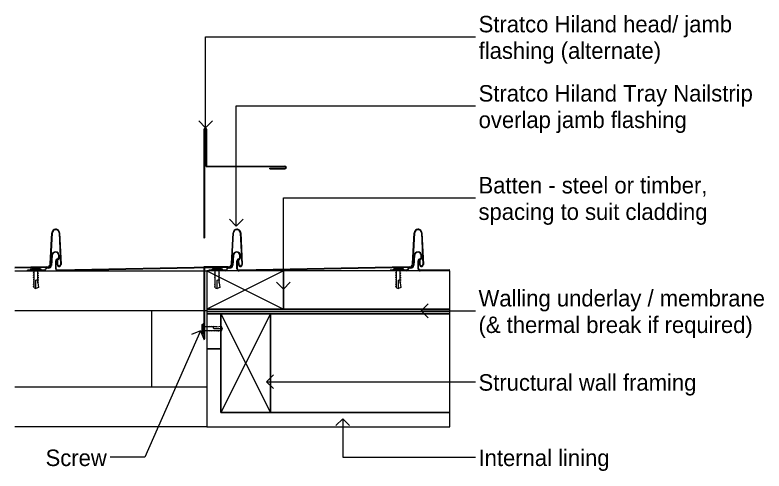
# Model space of a CAD drawing. Extents: x -2.36 to 6.66, y -3.72 to 4.13.
# Drawn here: x 5.981 to 6.663, y -2.182 to -1.767 of the extents above; entities that cross this region are included whole.
import ezdxf

# ---------------------------------------------------------------- set-up
doc = ezdxf.new("R2010")
doc.units = 0
for name, color, linetype in [('A-____-____-IDEN', 7, 'Continuous'), ('A-DETL-____-MEDM', 7, 'Continuous'), ('A-DETL-GENF-OTLN', 7, 'Continuous'), ('A-GLAZ-____-MCUT', 7, 'Continuous'), ('A-GLAZ-____-OTLN', 7, 'Continuous'), ('A-WALL-____-MCUT', 7, 'Continuous'), ('A-WALL-____-OTLN', 7, 'Continuous'), ('A-WALL-____-PATT', 7, 'Continuous'), ('A-WALL-FNSH-MCUT', 7, 'Continuous')]:
    doc.layers.add(name, color=color, linetype=linetype)

# ---------------------------------------------------------------- blocks, each defined once
blk = doc.blocks.new('Fixed - 1L _AUS_ - 1515-Detail Flashings - Hiland Nailstrip Jambs')
at = {"layer": 'A-GLAZ-____-MCUT'}
for p, q in [((-0.38883, 0.035), (-0.33883, 0.035)), ((-0.33883, 0.035), (-0.33883, -0.035)), ((-0.33883, -0.035), (-0.38883, -0.035))]:
    blk.add_line(p, q, dxfattribs=at)
at = {"layer": 'A-GLAZ-____-OTLN'}
for p, q in [((-0.33883, 0.035), (-0.21423, 0.035)), ((-0.21423, -0.035), (-0.33883, -0.035))]:
    blk.add_line(p, q, dxfattribs=at)
blk = doc.blocks.new('DET_ST_Framing Detail Timber - 35x70 Batten-Detail Flashings - Hiland Nailstrip Jambs')
at = {"layer": 'A-DETL-____-MEDM'}
for p, q in [((0.07, 0.035), (0, 0.035)), ((0, 0.035), (0, 0)), ((0.07, 0), (0.07, 0.035)), ((0, 0), (0.07, 0))]:
    blk.add_line(p, q, dxfattribs=at)
at = {"layer": 'A-DETL-GENF-OTLN'}
for p, q in [((0, 0.035), (0.07, 0)), ((0.07, 0.035), (0, 0))]:
    blk.add_line(p, q, dxfattribs=at)
blk = doc.blocks.new('Detail Repeating_Stratco_Hiland_Tray_Nailstrip - Rib Height 38mm_165mm Coverage-Detail Flashings - Hiland Nailstrip Jambs')
at = {"layer": 'A-DETL-____-MEDM'}
for p, q in [((0.17571, 0), (0.19057, 0)), ((0.19057, 0), (0.19057, -0.0005)), ((-0.00352, -0.03459), (-0.00483, -0.0057)), ((-0.00302, -0.03457), (-0.00433, -0.00568)), ((-0.00199, -0.00561), (-0.00187, -0.00979)), ((-0.00149, -0.0056), (-0.00137, -0.00977)), ((0.0045, -0.00635), (0.00302, -0.03464)), ((0.005, -0.00637), (0.00351, -0.03466)), ((0.008, -0.00303), (0.16297, 0)), ((0.008, -0.00353), (0.16298, -0.0005)), ((0.16148, -0.03459), (0.16017, -0.0057)), ((0.16198, -0.03457), (0.16067, -0.00568)), ((0.16301, -0.00561), (0.16313, -0.00979)), ((0.16351, -0.0056), (0.16363, -0.00977)), ((0.1645, -0.002), (0.1645, -0.00924)), ((0.165, -0.002), (0.165, -0.00924)), ((0.1695, -0.00635), (0.16802, -0.03464)), ((0.16814, -0.01418), (0.1688, -0.00504)), ((0.17, -0.00637), (0.16851, -0.03466)), ((0.16863, -0.01422), (0.16929, -0.00508)), ((0.17162, -0.00241), (0.17257, -0.00241)), ((0.17162, -0.00291), (0.17257, -0.00291)), ((0.173, -0.00303), (0.2021, -0.00246)), ((0.173, -0.00353), (0.2021, -0.00296)), ((0.17571, -0.0005), (0.19057, -0.0005)), ((-0.00137, -0.00977), (-0.00187, -0.00979)), ((0.16179, -0.01206), (0.16179, -0.01397)), ((0.16229, -0.01206), (0.16229, -0.01397)), ((0.16363, -0.00977), (0.16313, -0.00979))]:
    blk.add_line(p, q, dxfattribs=at)
for centre, radius, start, end in [((0.163, -0.002), 0.002, 360, 90), ((0.17571, -0.0019), 0.0019, 90, 165.08957), ((-0.00316, -0.00565), 0.00167, 91.69561, 181.73842), ((-0.00316, -0.00565), 0.00117, 91.68553, 181.57145), ((-0.00316, -0.00565), 0.00167, 1.72718, 91.74264), ((-0.00316, -0.00565), 0.00117, 1.72718, 91.75272), ((0.00799, -0.00653), 0.0035, 89.8838, 176.99932), ((0.00799, -0.00653), 0.003, 89.8838, 173.99932), ((0.16184, -0.00565), 0.00167, 91.69561, 181.73842), ((0.16184, -0.00565), 0.00117, 91.68553, 181.57145), ((0.16184, -0.00565), 0.00167, 1.72718, 91.74264), ((0.16184, -0.00565), 0.00117, 1.72718, 91.75272), ((0.163, -0.002), 0.0015, 360, 90), ((0.17162, -0.00525), 0.00283, 90, 175.86847), ((0.17162, -0.00525), 0.00233, 90, 175.86847), ((0.17299, -0.00653), 0.0035, 89.8838, 176.99932), ((0.17299, -0.00653), 0.003, 89.8838, 173.99932), ((0.17257, -0.00107), 0.00135, 270, 345.08957), ((0.17257, -0.00107), 0.00185, 270, 345.08957), ((0.17571, -0.0019), 0.0014, 90, 165.08957), ((0.16369, -0.01206), 0.0019, 97.16746, 180), ((0.16369, -0.01206), 0.0014, 99.15451, 180), ((0.16356, -0.00924), 0.000939, 263.63492, 0), ((0.16356, -0.00924), 0.00144, 266.42376, 0), ((0.16522, -0.01397), 0.00342, 180, 355.86847), ((0.16522, -0.01397), 0.00292, 180, 355.86847), ((0, -0.03448), 0.00352, 181.72283, 271.72823), ((0, -0.03448), 0.00302, 181.65349, 271.72911), ((0, -0.03448), 0.00302, 271.71675, 356.99932), ((0, -0.03448), 0.00352, 271.71763, 356.99932), ((0.165, -0.03448), 0.00352, 181.72283, 271.72823), ((0.165, -0.03448), 0.00302, 181.65349, 271.72911), ((0.165, -0.03448), 0.00302, 271.71675, 356.99932), ((0.165, -0.03448), 0.00352, 271.71763, 356.99932)]:
    blk.add_arc(centre, radius, start, end, dxfattribs=at)
at = {"layer": 'A-DETL-GENF-OTLN'}
for p, q in [((0.18068, 0.01509), (0.183, 0.01594)), ((0.18125, 0.01102), (0.18068, 0.01509)), ((0.183, 0.01594), (0.183, 0.00832)), ((0.18475, 0.0153), (0.183, 0.01594)), ((0.18475, 0.0153), (0.18475, 0.00022)), ((0.18475, 0.0146), (0.1855, 0.01436)), ((0.1805, 0.01068), (0.18125, 0.01044)), ((0.1805, 0.00858), (0.18125, 0.00834)), ((0.18125, 0.01102), (0.18125, 0.00022)), ((0.183, 0.00832), (0.18125, 0.00782)), ((0.18475, 0.0125), (0.1855, 0.01226)), ((0.18475, 0.0104), (0.1855, 0.01016)), ((0.18475, 0.0083), (0.1855, 0.00807)), ((0.1805, 0.00648), (0.18125, 0.00624)), ((0.1805, 0.00438), (0.18125, 0.00414)), ((0.1805, 0.00228), (0.18125, 0.00205)), ((0.18475, 0.00621), (0.1855, 0.00597)), ((0.18475, 0.00411), (0.1855, 0.00387)), ((0.18475, 0.00201), (0.1855, 0.00177)), ((0.17899, -0.00222), (0.17844, -0.00128)), ((0.17845, -0.00129), (0.18755, -0.00129)), ((0.1871, -0.00058), (0.1789, -0.00058)), ((0.18701, -0.00222), (0.17899, -0.00222)), ((0.18755, -0.00129), (0.18701, -0.00222))]:
    blk.add_line(p, q, dxfattribs=at)
for centre, radius, start, end in [((0.18045, 0.00022), 0.0008, 270, 360), ((0.18555, 0.00022), 0.0008, 180, 270), ((0.1789, -0.00108), 0.0005, 90, 203.66982), ((0.1871, -0.00108), 0.0005, 336.33018, 90)]:
    blk.add_arc(centre, radius, start, end, dxfattribs=at)
blk = doc.blocks.new('Detail Repeating_Stratco_Hiland_Tray_Nailstrip - Rib Height 38mm_165mm Coverage-V20-Detail Flashings - Hiland Nailstrip Jambs')
at = {"layer": 'A-DETL-____-MEDM'}
for p, q in [((3.64071, 0), (3.65557, 0)), ((3.65557, 0), (3.65557, -0.0005)), ((3.80571, 0), (3.82057, 0)), ((3.82057, 0), (3.82057, -0.0005)), ((3.6011, -0.00053), (3.62797, 0)), ((3.6011, -0.00103), (3.62798, -0.0005)), ((3.62648, -0.03459), (3.62517, -0.0057)), ((3.62698, -0.03457), (3.62567, -0.00568)), ((3.62801, -0.00561), (3.62813, -0.00979)), ((3.62851, -0.0056), (3.62863, -0.00977)), ((3.6295, -0.002), (3.6295, -0.00924)), ((3.63, -0.002), (3.63, -0.00924)), ((3.6345, -0.00635), (3.63302, -0.03464)), ((3.63314, -0.01418), (3.6338, -0.00504)), ((3.635, -0.00637), (3.63351, -0.03466)), ((3.63363, -0.01422), (3.63429, -0.00508)), ((3.63662, -0.00241), (3.63757, -0.00241)), ((3.63662, -0.00291), (3.63757, -0.00291)), ((3.638, -0.00303), (3.79297, 0)), ((3.638, -0.00353), (3.79298, -0.0005)), ((3.64071, -0.0005), (3.65557, -0.0005)), ((3.7945, -0.002), (3.7945, -0.00924)), ((3.795, -0.002), (3.795, -0.00924)), ((3.79814, -0.01418), (3.7988, -0.00504)), ((3.79863, -0.01422), (3.79929, -0.00508)), ((3.80162, -0.00241), (3.80257, -0.00241)), ((3.80162, -0.00291), (3.80257, -0.00291)), ((3.80571, -0.0005), (3.82057, -0.0005)), ((3.62679, -0.01206), (3.62679, -0.01397)), ((3.62729, -0.01206), (3.62729, -0.01397)), ((3.62863, -0.00977), (3.62813, -0.00979)), ((3.79179, -0.01206), (3.79179, -0.01397)), ((3.79229, -0.01206), (3.79229, -0.01397))]:
    blk.add_line(p, q, dxfattribs=at)
for centre, radius, start, end in [((3.628, -0.002), 0.002, 360, 90), ((3.64071, -0.0019), 0.0019, 90, 165.08957), ((3.793, -0.002), 0.002, 360, 90), ((3.80571, -0.0019), 0.0019, 90, 165.08957), ((3.62684, -0.00565), 0.00167, 91.69561, 181.73842), ((3.62684, -0.00565), 0.00117, 91.68553, 181.57145), ((3.62684, -0.00565), 0.00167, 1.72718, 91.74264), ((3.62684, -0.00565), 0.00117, 1.72718, 91.75272), ((3.628, -0.002), 0.0015, 0, 90), ((3.63662, -0.00525), 0.00283, 90, 175.86847), ((3.63662, -0.00525), 0.00233, 90, 175.86847), ((3.63799, -0.00653), 0.0035, 89.8838, 176.99932), ((3.63799, -0.00653), 0.003, 89.8838, 173.99932), ((3.63757, -0.00107), 0.00135, 270, 345.08957), ((3.63757, -0.00107), 0.00185, 270, 345.08957), ((3.64071, -0.0019), 0.0014, 90, 165.08957), ((3.793, -0.002), 0.0015, 0, 90), ((3.80162, -0.00525), 0.00283, 90, 175.86847), ((3.80162, -0.00525), 0.00233, 90, 175.86847), ((3.80257, -0.00107), 0.00135, 270, 345.08957), ((3.80257, -0.00107), 0.00185, 270, 345.08957), ((3.80571, -0.0019), 0.0014, 90, 165.08957), ((3.62869, -0.01206), 0.0019, 97.16746, 180), ((3.62869, -0.01206), 0.0014, 99.15451, 180), ((3.62856, -0.00924), 0.000939, 263.63492, 0), ((3.62856, -0.00924), 0.00144, 266.42376, 0), ((3.79369, -0.01206), 0.0019, 97.16746, 180), ((3.79369, -0.01206), 0.0014, 99.15451, 180), ((3.79356, -0.00924), 0.000939, 263.63492, 0), ((3.79356, -0.00924), 0.00144, 266.42376, 0), ((3.63022, -0.01397), 0.00342, 180, 355.86847), ((3.63022, -0.01397), 0.00292, 180, 355.86847), ((3.79522, -0.01397), 0.00342, 180, 355.86847), ((3.79522, -0.01397), 0.00292, 180, 355.86847), ((3.63, -0.03448), 0.00352, 181.72283, 271.72823), ((3.63, -0.03448), 0.00302, 181.65349, 271.72911), ((3.63, -0.03448), 0.00302, 271.71675, 356.99932), ((3.63, -0.03448), 0.00352, 271.71763, 356.99932)]:
    blk.add_arc(centre, radius, start, end, dxfattribs=at)
at = {"layer": 'A-DETL-GENF-OTLN'}
for p, q in [((3.64568, 0.01509), (3.648, 0.01594)), ((3.64625, 0.01102), (3.64568, 0.01509)), ((3.648, 0.01594), (3.648, 0.00832)), ((3.64975, 0.0153), (3.648, 0.01594)), ((3.64975, 0.0153), (3.64975, 0.00022)), ((3.64975, 0.0146), (3.6505, 0.01436)), ((3.81068, 0.01509), (3.813, 0.01594)), ((3.81125, 0.01102), (3.81068, 0.01509)), ((3.813, 0.01594), (3.813, 0.00832)), ((3.81475, 0.0153), (3.813, 0.01594)), ((3.81475, 0.0153), (3.81475, 0.00022)), ((3.81475, 0.0146), (3.8155, 0.01436)), ((3.6455, 0.01068), (3.64625, 0.01044)), ((3.6455, 0.00858), (3.64625, 0.00834)), ((3.64625, 0.01102), (3.64625, 0.00022)), ((3.648, 0.00832), (3.64625, 0.00782)), ((3.64975, 0.0125), (3.6505, 0.01226)), ((3.64975, 0.0104), (3.6505, 0.01016)), ((3.64975, 0.0083), (3.6505, 0.00807)), ((3.8105, 0.01068), (3.81125, 0.01044)), ((3.8105, 0.00858), (3.81125, 0.00834)), ((3.81125, 0.01102), (3.81125, 0.00022)), ((3.813, 0.00832), (3.81125, 0.00782)), ((3.81475, 0.0125), (3.8155, 0.01226)), ((3.81475, 0.0104), (3.8155, 0.01016)), ((3.81475, 0.0083), (3.8155, 0.00807)), ((3.6455, 0.00648), (3.64625, 0.00624)), ((3.6455, 0.00438), (3.64625, 0.00414)), ((3.6455, 0.00228), (3.64625, 0.00205)), ((3.64975, 0.00621), (3.6505, 0.00597)), ((3.64975, 0.00411), (3.6505, 0.00387)), ((3.64975, 0.00201), (3.6505, 0.00177)), ((3.8105, 0.00648), (3.81125, 0.00624)), ((3.8105, 0.00438), (3.81125, 0.00414)), ((3.8105, 0.00228), (3.81125, 0.00205)), ((3.81475, 0.00621), (3.8155, 0.00597)), ((3.81475, 0.00411), (3.8155, 0.00387)), ((3.81475, 0.00201), (3.8155, 0.00177)), ((3.64399, -0.00222), (3.64344, -0.00128)), ((3.64345, -0.00129), (3.65255, -0.00129)), ((3.6521, -0.00058), (3.6439, -0.00058)), ((3.65201, -0.00222), (3.64399, -0.00222)), ((3.65255, -0.00129), (3.65201, -0.00222)), ((3.80899, -0.00222), (3.80844, -0.00128)), ((3.80845, -0.00129), (3.81755, -0.00129)), ((3.8171, -0.00058), (3.8089, -0.00058)), ((3.81701, -0.00222), (3.80899, -0.00222)), ((3.81755, -0.00129), (3.81701, -0.00222))]:
    blk.add_line(p, q, dxfattribs=at)
for centre, radius, start, end in [((3.64545, 0.00022), 0.0008, 270, 360), ((3.65055, 0.00022), 0.0008, 180, 270), ((3.81045, 0.00022), 0.0008, 270, 360), ((3.81555, 0.00022), 0.0008, 180, 270), ((3.6439, -0.00108), 0.0005, 90, 203.66982), ((3.6521, -0.00108), 0.0005, 336.33018, 90), ((3.8089, -0.00108), 0.0005, 90, 203.66982), ((3.8171, -0.00108), 0.0005, 336.33018, 90)]:
    blk.add_arc(centre, radius, start, end, dxfattribs=at)
blk = doc.blocks.new('Detail_Stratco_Hiland_Tray_Nailstrip_Overlap Jamb - Rib Height 38mm-Detail Flashings - Hiland Nailstrip Jambs')
at = {"layer": 'A-DETL-GENF-OTLN'}
for p, q in [((-0.07959, 0.12638), (-0.07959, 0.19138)), ((-0.07959, 0.19138), (-0.07909, 0.19138)), ((-0.07909, 0.12588), (-0.07909, 0.19138)), ((-0.11261, 0.09482), (-0.11392, 0.12371)), ((-0.11211, 0.09484), (-0.11342, 0.12373)), ((-0.11108, 0.12379), (-0.11096, 0.11962)), ((-0.11058, 0.12381), (-0.11046, 0.11963)), ((-0.10459, 0.12306), (-0.10607, 0.09477)), ((-0.10408, 0.12311), (-0.10557, 0.09474)), ((-0.10109, 0.12638), (-0.07959, 0.12638)), ((-0.10109, 0.12588), (-0.07909, 0.12588)), ((-0.11096, 0.11962), (-0.11046, 0.11963))]:
    blk.add_line(p, q, dxfattribs=at)
for centre, radius, start, end in [((-0.11225, 0.12376), 0.00167, 91.69561, 181.73842), ((-0.11225, 0.12376), 0.00117, 91.68552, 181.57145), ((-0.11225, 0.12376), 0.00167, 1.72718, 91.74264), ((-0.11225, 0.12376), 0.00117, 1.72718, 91.75271), ((-0.10109, 0.12288), 0.0035, 89.8838, 176.99932), ((-0.1011, 0.12288), 0.003, 89.8838, 175.52401), ((-0.10909, 0.09493), 0.00352, 181.72283, 271.72967), ((-0.10909, 0.09493), 0.00302, 181.65349, 271.72911), ((-0.10909, 0.09493), 0.00302, 271.71675, 356.99932), ((-0.10909, 0.09493), 0.00352, 271.71907, 356.9938)]:
    blk.add_arc(centre, radius, start, end, dxfattribs=at)
blk = doc.blocks.new('DET_ST_Framing Detail Timber - 90x45-Detail Flashings - Hiland Nailstrip Jambs')
at = {"layer": 'A-DETL-____-MEDM'}
for p, q in [((0.045, 0.09), (0, 0.09)), ((0, 0.09), (0, 0)), ((0.045, 0), (0.045, 0.09)), ((0, 0), (0.045, 0))]:
    blk.add_line(p, q, dxfattribs=at)
at = {"layer": 'A-DETL-GENF-OTLN'}
for p, q in [((0, 0.09), (0.045, 0)), ((0.045, 0.09), (0, 0))]:
    blk.add_line(p, q, dxfattribs=at)
blk = doc.blocks.new('DET_Screw Metal Wafer - DET_Screw Metal Wafer-Detail Flashings - Hiland Nailstrip Jambs')
at = {"layer": 'A-DETL-GENF-OTLN'}
for p, q in [((-0.00455, 0.00071), (-0.00401, 0.00164)), ((0.00455, 0.00071), (-0.00455, 0.00071)), ((-0.00401, 0.00164), (0.00401, 0.00164)), ((0.00401, 0.00164), (0.00456, 0.0007)), ((-0.0041, 0), (0.0041, 0)), ((-0.00175, -0.00259), (-0.0025, -0.00235)), ((-0.00175, -0.00468), (-0.0025, -0.00445)), ((-0.00175, -0.00678), (-0.0025, -0.00654)), ((-0.00175, -0.01588), (-0.00175, -0.0008)), ((0.00175, -0.0116), (0.00175, -0.0008)), ((0.0025, -0.00286), (0.00175, -0.00262)), ((0.0025, -0.00496), (0.00175, -0.00472)), ((0.0025, -0.00706), (0.00175, -0.00682)), ((-0.00175, -0.00888), (-0.0025, -0.00864)), ((-0.00175, -0.01098), (-0.0025, -0.01074)), ((-0.00175, -0.01308), (-0.0025, -0.01284)), ((0, -0.0089), (0.00175, -0.0084)), ((0, -0.01651), (0, -0.0089)), ((0.0025, -0.00915), (0.00175, -0.00892)), ((0.0025, -0.01125), (0.00175, -0.01102)), ((0.00175, -0.0116), (0.00232, -0.01567)), ((-0.00175, -0.01518), (-0.0025, -0.01494)), ((-0.00175, -0.01588), (0, -0.01651)), ((0.00232, -0.01567), (0, -0.01651))]:
    blk.add_line(p, q, dxfattribs=at)
for centre, radius, start, end in [((-0.0041, 0.0005), 0.0005, 156.33018, 270), ((-0.00255, -0.0008), 0.0008, 360, 90), ((0.00255, -0.0008), 0.0008, 90, 180), ((0.0041, 0.0005), 0.0005, 270, 23.66982)]:
    blk.add_arc(centre, radius, start, end, dxfattribs=at)
blk = doc.blocks.new('Detail_Stratco_Hiland_Tray_Head Jamb - Rib Height 25mm-Detail Flashings - Hiland Nailstrip Jambs')
at = {"layer": 'A-DETL-GENF-OTLN'}
for p, q in [((-0.06845, -0.14295), (-0.06845, -0.0717)), ((-0.06795, -0.14345), (-0.06795, -0.0717)), ((-0.06645, -0.08545), (-0.06645, -0.0717)), ((-0.06595, -0.08545), (-0.06595, -0.0717)), ((-0.06595, -0.08545), (-0.06645, -0.08545)), ((-0.06845, -0.14295), (-0.1017, -0.14295)), ((-0.06795, -0.14345), (-0.1017, -0.14345)), ((-0.1017, -0.14495), (-0.00295, -0.14495)), ((-0.1017, -0.14545), (-0.00295, -0.14545)), ((-0.00295, -0.14545), (-0.00295, -0.14495))]:
    blk.add_line(p, q, dxfattribs=at)
for centre, radius, start, end in [((-0.0672, -0.0717), 0.00125, 0, 180), ((-0.0672, -0.0717), 0.00075, 0, 180), ((-0.1017, -0.1442), 0.00125, 90, 270), ((-0.1017, -0.1442), 0.00075, 90, 270)]:
    blk.add_arc(centre, radius, start, end, dxfattribs=at)

msp = doc.modelspace()

# ---------------------------------------------------------------- linework, layer by layer
at = {"layer": 'A-____-____-IDEN'}
for p, q in [((6.15481, -1.78672), (6.40071, -1.78672)), ((6.15481, -1.86971), (6.15481, -1.78672)), ((6.18269, -1.84976), (6.40071, -1.84976)), ((6.18269, -1.95921), (6.18269, -1.84976)), ((6.15481, -1.86971), (6.14856, -1.86346)), ((6.15481, -1.86971), (6.16106, -1.86346)), ((6.22562, -1.93345), (6.40071, -1.93345)), ((6.22562, -2.01661), (6.22562, -1.93345)), ((6.18269, -1.95921), (6.17644, -1.95296)), ((6.18269, -1.95921), (6.18894, -1.95296)), ((6.22562, -2.01661), (6.21937, -2.01036)), ((6.22562, -2.01661), (6.23187, -2.01036)), ((6.35125, -2.03641), (6.3575, -2.03016)), ((6.35125, -2.03641), (6.3575, -2.04266)), ((6.35125, -2.03641), (6.36038, -2.03641)), ((6.36038, -2.03641), (6.40071, -2.03641)), ((6.1503, -2.05465), (6.09951, -2.16966)), ((6.1503, -2.05465), (6.14206, -2.05784)), ((6.1503, -2.05465), (6.15349, -2.06289)), ((6.21039, -2.10102), (6.21664, -2.09477)), ((6.21039, -2.10102), (6.21664, -2.10727)), ((6.21039, -2.10102), (6.40071, -2.10102)), ((6.27968, -2.13463), (6.27343, -2.14088)), ((6.27968, -2.13463), (6.28593, -2.14088)), ((6.27968, -2.13463), (6.27968, -2.16966)), ((6.09951, -2.16966), (6.06799, -2.16966)), ((6.27968, -2.16966), (6.40071, -2.16966))]:
    msp.add_line(p, q, dxfattribs=at)
at = {"layer": 'A-WALL-____-MCUT'}
for p, q in [((6.37722, -2), (6.22582, -2)), ((6.15582, -2.035), (6.15582, -2.071)), ((6.37722, -2.037), (6.15582, -2.037)), ((6.16882, -2.039), (6.15582, -2.039)), ((6.37722, -2.039), (6.21382, -2.039)), ((6.37722, -2.035), (6.22582, -2.035)), ((6.16882, -2.071), (6.15582, -2.071)), ((6.21382, -2.129), (6.37722, -2.129))]:
    msp.add_line(p, q, dxfattribs=at)
at = {"layer": 'A-WALL-____-OTLN'}
for p, q in [((5.98123, -2), (6.15582, -2)), ((6.15582, -2.142), (5.98123, -2.142))]:
    msp.add_line(p, q, dxfattribs=at)
at = {"layer": 'A-WALL-____-PATT'}
for p, q in [((6.37722, -2), (6.22582, -2)), ((6.22582, -2), (6.22582, -2.035)), ((6.37722, -2.035), (6.37722, -2)), ((6.37722, -2.035), (6.15582, -2.035)), ((6.15582, -2.035), (6.15582, -2.037)), ((6.15582, -2.037), (6.37722, -2.037)), ((6.37722, -2.037), (6.15582, -2.037)), ((6.15582, -2.037), (6.15582, -2.039)), ((6.15582, -2.039), (6.16882, -2.039)), ((6.16882, -2.039), (6.15582, -2.039)), ((6.15582, -2.039), (6.15582, -2.071)), ((6.16882, -2.039), (6.37722, -2.039)), ((6.16882, -2.071), (6.16882, -2.039)), ((6.37722, -2.039), (6.21382, -2.039)), ((6.21382, -2.039), (6.21382, -2.129)), ((6.22582, -2.035), (6.37722, -2.035)), ((6.37722, -2.037), (6.37722, -2.035)), ((6.37722, -2.039), (6.37722, -2.037)), ((6.37722, -2.129), (6.37722, -2.039)), ((6.15582, -2.071), (6.16882, -2.071)), ((6.16882, -2.071), (6.15582, -2.071)), ((6.15582, -2.071), (6.15582, -2.129)), ((6.16882, -2.129), (6.16882, -2.071)), ((6.15582, -2.129), (6.15582, -2.142)), ((6.37722, -2.129), (6.16882, -2.129)), ((6.21382, -2.129), (6.37722, -2.129)), ((6.37722, -2.142), (6.37722, -2.129)), ((6.15582, -2.142), (6.37722, -2.142))]:
    msp.add_line(p, q, dxfattribs=at)
at = {"layer": 'A-WALL-FNSH-MCUT'}
for p, q in [((6.15582, -2.071), (6.15582, -2.142)), ((6.15582, -2.142), (6.37722, -2.142))]:
    msp.add_line(p, q, dxfattribs=at)

# ---------------------------------------------------------------- block references
at = {"layer": 'A-DETL-GENF-OTLN'}
for name, p, rotation in [('Detail_Stratco_Hiland_Tray_Head Jamb - Rib Height 25mm-Detail Flashings - Hiland Nailstrip Jambs', (6.29878, -1.97295), -90.00000000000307), ('Detail Repeating_Stratco_Hiland_Tray_Nailstrip - Rib Height 38mm_165mm Coverage-Detail Flashings - Hiland Nailstrip Jambs', (6.18332, -2), 180), ('Detail_Stratco_Hiland_Tray_Nailstrip_Overlap Jamb - Rib Height 38mm-Detail Flashings - Hiland Nailstrip Jambs', (6.07423, -1.87059), 180), ('Detail Repeating_Stratco_Hiland_Tray_Nailstrip - Rib Height 38mm_165mm Coverage-V20-Detail Flashings - Hiland Nailstrip Jambs', (9.97832, -2), 180), ('DET_Screw Metal Wafer - DET_Screw Metal Wafer-Detail Flashings - Hiland Nailstrip Jambs', (6.15332, -2.05279), 89.99999999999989)]:
    msp.add_blockref(name, p, dxfattribs=dict(at, rotation=rotation))
for name, p in [('DET_ST_Framing Detail Timber - 35x70 Batten-Detail Flashings - Hiland Nailstrip Jambs', (6.15582, -2.035)), ('DET_ST_Framing Detail Timber - 90x45-Detail Flashings - Hiland Nailstrip Jambs', (6.16882, -2.129))]:
    msp.add_blockref(name, p, dxfattribs=at)
at = {"layer": 'A-GLAZ-____-OTLN', "rotation": 180}
msp.add_blockref('Fixed - 1L _AUS_ - 1515-Detail Flashings - Hiland Nailstrip Jambs', (5.767, -2.071), dxfattribs=at)

# ---------------------------------------------------------------- texts
at = {"layer": 'A-____-____-IDEN'}
for s, p in [('Stratco Hiland head/ jamb', (6.40343, -1.78275)), ('flashing (alternate)', (6.40343, -1.80689)), ('Stratco Hiland Tray Nailstrip', (6.40343, -1.84579)), ('overlap jamb flashing', (6.40343, -1.86993)), ('Batten - steel or timber,', (6.40333, -1.92948)), ('spacing to suit cladding', (6.40333, -1.95362)), ('Walling underlay / membrane', (6.40333, -2.03243)), ('(& thermal break if required)', (6.40333, -2.05658)), ('Structural wall framing', (6.40333, -2.10912)), ('Internal lining', (6.40333, -2.17776)), ('Screw', (6.00909, -2.17776))]:
    msp.add_text(s, height=0.015, dxfattribs=at).set_placement(p)

doc.saveas('drawing.dxf')
